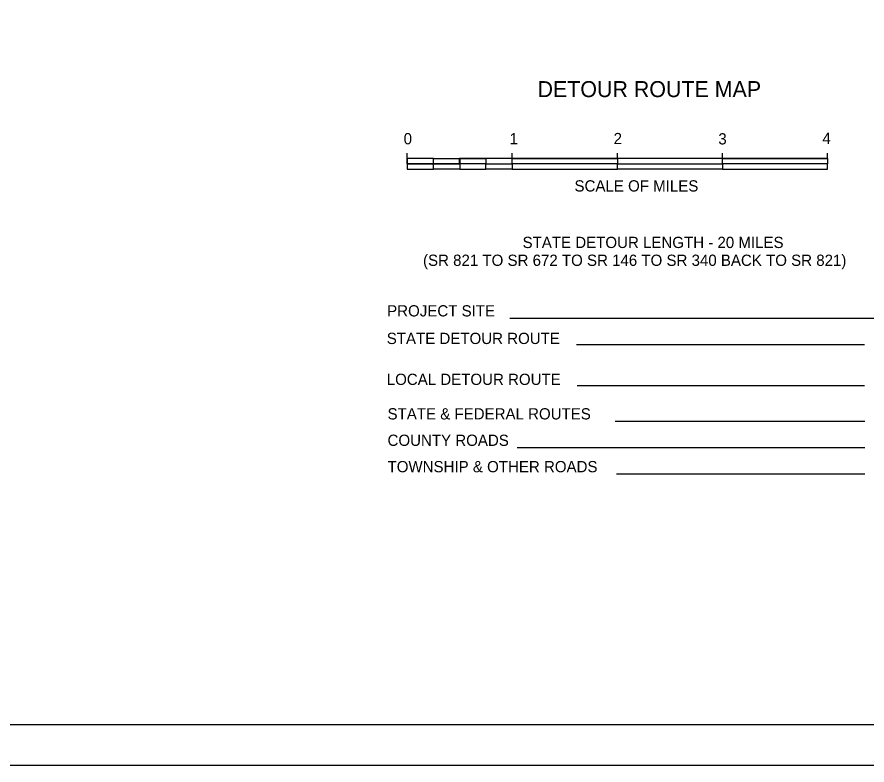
# Model space of a CAD drawing. Extents: x 0 to 34, y 0 to 22.
# Drawn here: x 17 to 27.57, y 0 to 9.3 of the extents above; entities that cross this region are included whole.
import ezdxf

# ---------------------------------------------------------------- set-up
doc = ezdxf.new("R2010")
doc.units = 0
for name, color, linetype in [('Default', 7, 'Continuous'), ('SH_Border', 7, 'Continuous'), ('SH_Cut_Line', 7, 'Continuous'), ('TX_P_1', 7, 'Continuous')]:
    doc.layers.add(name, color=color, linetype=linetype)

msp = doc.modelspace()

# ---------------------------------------------------------------- linework, layer by layer
at = {"layer": 'Default'}
for p, q in [((21.852, 7.542), (21.852, 7.61)), ((22.178, 7.544), (21.852, 7.544)), ((21.852, 7.479), (21.852, 7.542)), ((22.178, 7.544), (22.504, 7.544)), ((22.179, 7.479), (22.179, 7.544)), ((22.832, 7.544), (22.504, 7.544)), ((22.506, 7.544), (22.506, 7.479)), ((22.832, 7.544), (22.832, 7.479)), ((23.159, 7.544), (22.832, 7.544)), ((23.159, 7.544), (23.159, 7.61)), ((23.159, 7.479), (23.159, 7.544)), ((24.466, 7.544), (23.159, 7.544)), ((24.466, 7.544), (24.466, 7.61)), ((25.772, 7.544), (24.466, 7.544)), ((24.466, 7.544), (24.466, 7.479)), ((25.772, 7.544), (25.772, 7.61)), ((25.772, 7.479), (25.772, 7.544)), ((27.079, 7.544), (25.772, 7.544)), ((27.079, 7.544), (27.079, 7.61)), ((27.079, 7.544), (27.079, 7.479)), ((22.179, 7.479), (21.852, 7.479)), ((21.852, 7.479), (21.852, 7.413)), ((21.852, 7.413), (22.18, 7.413)), ((22.506, 7.479), (22.179, 7.479)), ((22.179, 7.413), (22.179, 7.479)), ((22.506, 7.413), (22.18, 7.413)), ((22.832, 7.479), (22.506, 7.479)), ((22.506, 7.479), (22.506, 7.413)), ((22.506, 7.413), (22.831, 7.413)), ((23.159, 7.413), (22.831, 7.413)), ((22.832, 7.413), (22.832, 7.479)), ((22.832, 7.479), (23.159, 7.479)), ((24.466, 7.479), (23.159, 7.479)), ((23.159, 7.479), (23.159, 7.413)), ((23.159, 7.413), (24.466, 7.413)), ((24.466, 7.413), (24.466, 7.479)), ((24.466, 7.479), (25.772, 7.479)), ((25.772, 7.413), (24.466, 7.413)), ((27.079, 7.479), (25.772, 7.479)), ((25.772, 7.479), (25.772, 7.413)), ((25.772, 7.413), (27.079, 7.413)), ((27.079, 7.413), (27.079, 7.479)), ((28.148, 5.555), (23.13, 5.555)), ((27.538, 5.226), (23.958, 5.226)), ((27.538, 4.717), (23.968, 4.717)), ((27.544, 4.274), (24.439, 4.274)), ((27.544, 3.945), (23.22, 3.945)), ((27.544, 3.616), (24.454, 3.616))]:
    msp.add_line(p, q, dxfattribs=at)
for points in [[(22.178, 7.544), (21.852, 7.544), (21.852, 7.479), (22.178, 7.479)], [(22.504, 7.544), (22.832, 7.544), (22.832, 7.479), (22.504, 7.479)], [(23.159, 7.544), (24.466, 7.544), (24.466, 7.479), (23.159, 7.479)], [(25.772, 7.544), (27.079, 7.544), (27.079, 7.479), (25.772, 7.479)], [(22.179, 7.479), (22.506, 7.479), (22.506, 7.413), (22.179, 7.413)], [(22.832, 7.479), (23.159, 7.479), (23.159, 7.413), (22.832, 7.413)], [(24.466, 7.479), (25.772, 7.479), (25.772, 7.413), (24.466, 7.413)]]:
    msp.add_lwpolyline(points, close=True, dxfattribs=at)
at = {"layer": 'SH_Border'}
msp.add_lwpolyline([(1.5, 21.5), (33.5, 21.5), (33.5, 0.5), (1.5, 0.5)], close=True, dxfattribs=at)
at = {"layer": 'SH_Cut_Line'}
msp.add_lwpolyline([(0, 0), (34, 0), (34, 22), (0, 22)], close=True, dxfattribs=at)

# ---------------------------------------------------------------- texts
at = {"layer": 'TX_P_1'}
for s, height, p in [('DETOUR ROUTE MAP', 0.19905, (23.473, 8.307)), ('0', 0.14, (21.808, 7.72)), ('1', 0.14, (23.125, 7.72)), ('2', 0.14, (24.419, 7.722)), ('3', 0.14, (25.721, 7.718)), ('4', 0.14, (27.015, 7.724)), ('SCALE OF MILES', 0.14, (23.933, 7.133)), ('STATE DETOUR LENGTH - 20 MILES', 0.14, (23.287, 6.43)), ('(SR 821 TO SR 672 TO SR 146 TO SR 340 BACK TO SR 821)', 0.14, (22.049, 6.208)), ('PROJECT SITE', 0.14, (21.603, 5.579)), ('STATE DETOUR ROUTE', 0.14, (21.598, 5.236)), ('LOCAL DETOUR ROUTE', 0.14, (21.598, 4.727)), ('STATE & FEDERAL ROUTES', 0.14, (21.608, 4.298)), ('COUNTY ROADS', 0.14, (21.608, 3.969)), ('TOWNSHIP & OTHER ROADS', 0.14, (21.608, 3.641))]:
    msp.add_text(s, height=height, dxfattribs=at).set_placement(p)

doc.saveas('drawing.dxf')
